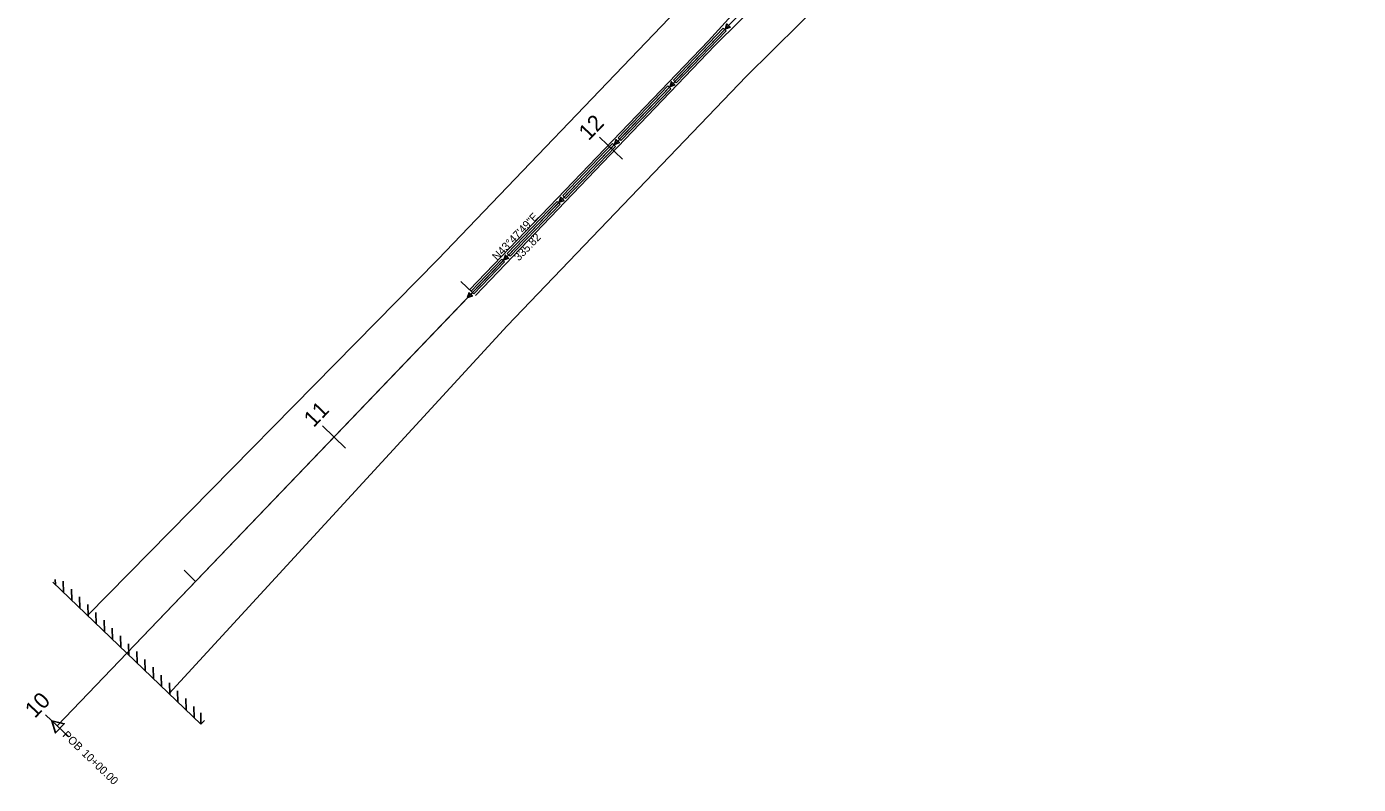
# Model space of a CAD drawing. Extents: x 2377903 to 2496516, y 664638 to 732785.
# Drawn here: x 2377903 to 2378235.8, y 730079.8 to 730269.2 of the extents above; entities that cross this region are included whole.
import ezdxf

# ---------------------------------------------------------------- set-up
doc = ezdxf.new("R2010")
doc.units = 0
for name, color, linetype in [('ALG_CL_BLUE_Horiz', 7, 'Continuous'), ('ALG_CL_BLUE_Horiz-Stationing', 7, 'Continuous'), ('ALG_CL_BLUE_Horiz-Text', 7, 'Continuous'), ('DES_ROADWAY_Curb-Back', 7, 'Continuous'), ('DES_ROADWAY_Curb-Face', 7, 'Continuous'), ('DES_ROADWAY_Edge-of-Pavement', 7, 'Continuous'), ('DES_ROADWAY_Misc-SAW CUT', 7, 'Continuous'), ('TRAF_PAVEMARK_White_SKIP 12-38', 7, 'Continuous'), ('TRAF_PAVEMARK_Yellow', 7, 'Continuous'), ('TRAF_PAVEMARK_Yellow-DBL YELLOW', 7, 'Continuous'), ('TRAF_WORKZONE_Drum', 7, 'Continuous')]:
    doc.layers.add(name, color=color, linetype=linetype)

msp = doc.modelspace()

# ---------------------------------------------------------------- linework, layer by layer
at = {"layer": 'ALG_CL_BLUE_Horiz'}
msp.add_line((2377910.62, 730094.46), (2378143.04, 730336.85), dxfattribs=at)
at = {"layer": 'ALG_CL_BLUE_Horiz-Stationing'}
for p, q in [((2378046.15, 730241.58), (2378051.93, 730236.05)), ((2378011.55, 730205.49), (2378014.43, 730202.73)), ((2377976.94, 730169.4), (2377982.72, 730163.87)), ((2377942.34, 730133.31), (2377945.22, 730130.55)), ((2377907.73, 730097.22), (2377913.5, 730091.69))]:
    msp.add_line(p, q, dxfattribs=at)
msp.add_lwpolyline([(2377909.28, 730095.73), (2377910.18, 730092.66), (2377912.39, 730094.97)], close=True, dxfattribs=at)
at = {"layer": 'DES_ROADWAY_Curb-Back'}
for p, q in [((2378077.47, 730268.46), (2378065.01, 730255.47)), ((2378063.63, 730254.03), (2378051.17, 730241.04)), ((2378049.78, 730239.59), (2378037.33, 730226.6)), ((2378035.94, 730225.16), (2378023.48, 730212.16)), ((2378022.1, 730210.72), (2378014.43, 730202.73))]:
    msp.add_line(p, q, dxfattribs=at)
at = {"layer": 'DES_ROADWAY_Curb-Face'}
for p, q in [((2378077.11, 730268.81), (2378064.65, 730255.82)), ((2378077.83, 730268.12), (2378065.37, 730255.13)), ((2378077.11, 730268.81), (2378077.83, 730268.12)), ((2378063.27, 730254.37), (2378050.81, 730241.38)), ((2378063.27, 730254.37), (2378063.99, 730253.68)), ((2378064.65, 730255.82), (2378065.37, 730255.13)), ((2378063.99, 730253.68), (2378051.53, 730240.69)), ((2378050.81, 730241.38), (2378051.53, 730240.69)), ((2378049.42, 730239.94), (2378036.97, 730226.95)), ((2378050.14, 730239.25), (2378037.69, 730226.25)), ((2378049.42, 730239.94), (2378050.14, 730239.25)), ((2378035.58, 730225.5), (2378023.12, 730212.51)), ((2378036.3, 730224.81), (2378023.84, 730211.82)), ((2378035.58, 730225.5), (2378036.3, 730224.81)), ((2378036.97, 730226.95), (2378037.69, 730226.25)), ((2378021.74, 730211.07), (2378014.07, 730203.07)), ((2378021.74, 730211.07), (2378022.46, 730210.37)), ((2378023.12, 730212.51), (2378023.84, 730211.82)), ((2378022.46, 730210.37), (2378014.79, 730202.38)), ((2378014.07, 730203.07), (2378014.79, 730202.38))]:
    msp.add_line(p, q, dxfattribs=at)
at = {"layer": 'DES_ROADWAY_Edge-of-Pavement'}
for p, q in [((2377909.5, 730130.37), (2377946.56, 730094.86)), ((2377946.56, 730094.86), (2377947.41, 730095.75))]:
    msp.add_line(p, q, dxfattribs=at)
at = {"layer": 'DES_ROADWAY_Misc-SAW CUT'}
for p, q in [((2377910.17, 730129.73), (2377910.14, 730131.03)), ((2377912.21, 730127.77), (2377912.15, 730130.6)), ((2377914.25, 730125.81), (2377914.19, 730128.64)), ((2377916.29, 730123.86), (2377916.23, 730126.68)), ((2377918.34, 730121.9), (2377918.28, 730124.73)), ((2377920.38, 730119.94), (2377920.32, 730122.77)), ((2377922.42, 730117.99), (2377922.36, 730120.82)), ((2377924.46, 730116.03), (2377924.4, 730118.86)), ((2377926.5, 730114.08), (2377926.44, 730116.9)), ((2377928.54, 730112.12), (2377928.48, 730114.95)), ((2377930.59, 730110.16), (2377930.53, 730112.99)), ((2377932.63, 730108.21), (2377932.57, 730111.03)), ((2377934.67, 730106.25), (2377934.61, 730109.08)), ((2377936.71, 730104.29), (2377936.65, 730107.12)), ((2377938.75, 730102.34), (2377938.69, 730105.16)), ((2377940.79, 730100.38), (2377940.73, 730103.21)), ((2377942.84, 730098.42), (2377942.78, 730101.25)), ((2377944.88, 730096.47), (2377944.82, 730099.29)), ((2377946.55, 730094.86), (2377946.49, 730097.69))]:
    msp.add_line(p, q, dxfattribs=at)
at = {"layer": 'TRAF_PAVEMARK_White_SKIP 12-38'}
for p, q in [((2378082.74, 730256.63), (2378235.84, 730408.38)), ((2378065.48, 730273.3), (2378005.77, 730211.03)), ((2378082.93, 730256.83), (2378023.09, 730194.42)), ((2377918.22, 730122.01), (2378005.77, 730211.03)), ((2377938.59, 730102.49), (2378023.09, 730194.42))]:
    msp.add_line(p, q, dxfattribs=at)
at = {"layer": 'TRAF_PAVEMARK_Yellow'}
for p, q in [((2378218.65, 730425.15), (2378073.42, 730265.68)), ((2378074.99, 730264.44), (2378227.99, 730416.1)), ((2378073.42, 730265.68), (2378013.71, 730203.42)), ((2378074.99, 730264.44), (2378015.15, 730202.03))]:
    msp.add_line(p, q, dxfattribs=at)
at = {"layer": 'TRAF_PAVEMARK_Yellow-DBL YELLOW'}
msp.add_line((2378014.43, 730202.73), (2377928.03, 730112.61), dxfattribs=at)
at = {"layer": 'TRAF_WORKZONE_Drum'}
for points in [[(2378077.64, 730268.65), (2378078.01, 730269.85), (2378078.83, 730269.07)], [(2378063.8, 730254.21), (2378064.17, 730255.41), (2378064.98, 730254.63)], [(2378049.96, 730239.77), (2378050.33, 730240.97), (2378051.14, 730240.2)], [(2378036.11, 730225.34), (2378036.49, 730226.54), (2378037.3, 730225.76)], [(2378022.27, 730210.9), (2378022.65, 730212.1), (2378023.46, 730211.32)], [(2378013.22, 730201.46), (2378013.59, 730202.66), (2378014.41, 730201.88)]]:
    msp.add_lwpolyline(points, close=True, dxfattribs=at)

# ---------------------------------------------------------------- texts
at = {"layer": 'ALG_CL_BLUE_Horiz-Stationing'}
for s, p in [('12', (2378043.46, 730240.52)), ('11', (2377974.74, 730168.85)), ('10', (2377905.06, 730096.17))]:
    msp.add_text(s, height=4, rotation=46.2032, dxfattribs=at).set_placement(p)
at = {"layer": 'ALG_CL_BLUE_Horiz-Text'}
for s, rotation, p in [('N43°47\'49"E', 46.2032, (2378020.58, 730210.58)), ('335.82', 46.2032, (2378026.03, 730210.49)), ('POB ', 316.2032, (2377911.8, 730091.93)), ('10+00.00', 316.2032, (2377916.62, 730087.31))]:
    msp.add_text(s, height=2, rotation=rotation, dxfattribs=at).set_placement(p)

doc.saveas('drawing.dxf')
